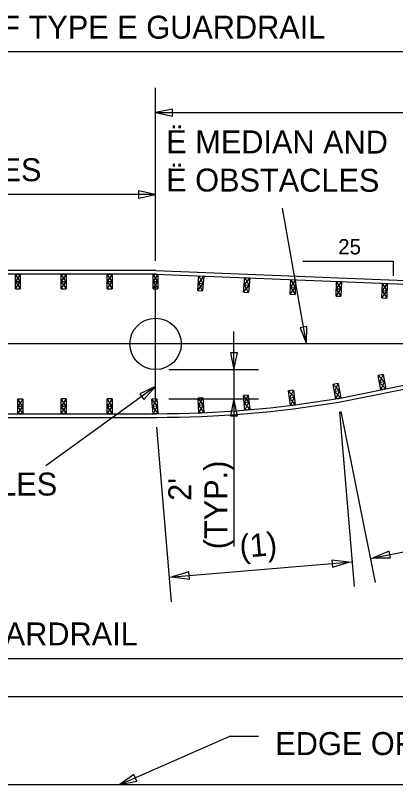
# Model space of a CAD drawing. Extents: x -439.1 to -407.9, y -458.1 to -436.2.
# Drawn here: x -423.51 to -421.03, y -445.9 to -440.88 of the extents above; entities that cross this region are included whole.
import ezdxf

# ---------------------------------------------------------------- set-up
doc = ezdxf.new("R2010")
doc.units = 0
doc.layers.add('Default', color=7, linetype='Continuous')

msp = doc.modelspace()

# ---------------------------------------------------------------- linework, layer by layer
at = {"layer": 'Default'}
for p, q in [((-419.0018, -441.115), (-427.37, -441.115)), ((-422.5989, -442.4799), (-422.5989, -441.3503)), ((-422.5989, -441.5115), (-419.0018, -441.5115)), ((-422.5989, -442.047), (-424.9989, -442.047)), ((-421.6129, -443.0234), (-421.7698, -442.1369)), ((-421.637, -442.4823), (-421.045, -442.4823)), ((-421.045, -442.4823), (-421.045, -442.5783)), ((-422.598, -442.5433), (-425.002, -442.5433)), ((-422.598, -442.5433), (-413.602, -442.9033)), ((-422.599, -442.5673), (-424.999, -442.5673)), ((-423.5148, -442.5674), (-423.4829, -442.5674)), ((-423.4829, -442.6154), (-423.5148, -442.5674)), ((-423.4829, -442.5674), (-423.5148, -442.6154)), ((-423.5148, -442.6634), (-423.5148, -442.5674)), ((-423.4989, -442.5674), (-423.4989, -442.5674)), ((-423.4829, -442.5674), (-423.4829, -442.5674)), ((-423.4829, -442.5674), (-423.4829, -442.6634)), ((-423.2149, -442.5674), (-423.1829, -442.5674)), ((-423.1829, -442.6154), (-423.2149, -442.5674)), ((-423.1829, -442.5674), (-423.2149, -442.6154)), ((-423.2149, -442.6634), (-423.2149, -442.5674)), ((-423.1989, -442.5674), (-423.1989, -442.5674)), ((-423.1829, -442.5674), (-423.1829, -442.5674)), ((-423.1829, -442.5674), (-423.1829, -442.6634)), ((-422.9149, -442.5674), (-422.8829, -442.5674)), ((-422.8829, -442.6154), (-422.9149, -442.5674)), ((-422.8829, -442.5674), (-422.9149, -442.6154)), ((-422.9149, -442.6634), (-422.9149, -442.5674)), ((-422.8989, -442.5674), (-422.8989, -442.5674)), ((-422.8829, -442.5674), (-422.8829, -442.5674)), ((-422.8829, -442.5674), (-422.8829, -442.6634)), ((-422.6149, -442.5674), (-422.5829, -442.5674)), ((-422.5829, -442.6154), (-422.6149, -442.5674)), ((-422.5829, -442.5674), (-422.6149, -442.6154)), ((-422.6149, -442.6634), (-422.6149, -442.5674)), ((-422.599, -442.5673), (-413.603, -442.9273)), ((-422.5989, -442.5674), (-422.5989, -442.5674)), ((-422.5829, -442.5674), (-422.5829, -442.5674)), ((-422.5829, -442.5674), (-422.5829, -442.6634)), ((-422.3234, -442.6736), (-422.3151, -442.578)), ((-422.2832, -442.5807), (-422.3192, -442.6258)), ((-422.3151, -442.578), (-422.2832, -442.5807)), ((-422.2874, -442.6286), (-422.3151, -442.578)), ((-422.2991, -442.5794), (-422.2991, -442.5794)), ((-422.2832, -442.5807), (-422.2915, -442.6764)), ((-422.2832, -442.5807), (-422.2832, -442.5807)), ((-422.0237, -442.6856), (-422.0153, -442.5899)), ((-421.9834, -442.5927), (-422.0195, -442.6378)), ((-422.0153, -442.5899), (-421.9834, -442.5927)), ((-421.9876, -442.6405), (-422.0153, -442.5899)), ((-421.9994, -442.5913), (-421.9994, -442.5913)), ((-421.9834, -442.5927), (-421.9918, -442.6884)), ((-421.9834, -442.5927), (-421.9834, -442.5927)), ((-421.7189, -442.6987), (-421.7156, -442.6028)), ((-421.6836, -442.6039), (-421.7173, -442.6507)), ((-421.7156, -442.6028), (-421.6836, -442.6039)), ((-421.6853, -442.6519), (-421.7156, -442.6028)), ((-421.6996, -442.6033), (-421.6996, -442.6033)), ((-421.6836, -442.6039), (-421.687, -442.6998)), ((-421.6836, -442.6039), (-421.6836, -442.6039)), ((-423.5148, -442.6154), (-423.4829, -442.6154)), ((-423.5148, -442.6634), (-423.4829, -442.6154)), ((-423.5148, -442.6154), (-423.4829, -442.6634)), ((-423.2149, -442.6154), (-423.1829, -442.6154)), ((-423.2149, -442.6634), (-423.1829, -442.6154)), ((-423.2149, -442.6154), (-423.1829, -442.6634)), ((-422.9149, -442.6154), (-422.8829, -442.6154)), ((-422.9149, -442.6634), (-422.8829, -442.6154)), ((-422.9149, -442.6154), (-422.8829, -442.6634)), ((-422.6149, -442.6154), (-422.5829, -442.6154)), ((-422.6149, -442.6634), (-422.5829, -442.6154)), ((-422.6149, -442.6154), (-422.5829, -442.6634)), ((-422.599, -443.3993), (-422.599, -442.6373)), ((-422.3234, -442.6736), (-422.2874, -442.6286)), ((-422.3192, -442.6258), (-422.2874, -442.6286)), ((-422.3192, -442.6258), (-422.2915, -442.6764)), ((-422.0237, -442.6856), (-421.9876, -442.6405)), ((-422.0195, -442.6378), (-421.9876, -442.6405)), ((-422.0195, -442.6378), (-421.9918, -442.6884)), ((-421.7189, -442.6987), (-421.6853, -442.6519)), ((-421.7173, -442.6507), (-421.6853, -442.6519)), ((-421.7173, -442.6507), (-421.687, -442.6998)), ((-421.4192, -442.7107), (-421.4158, -442.6148)), ((-421.3838, -442.6159), (-421.4175, -442.6627)), ((-421.4158, -442.6148), (-421.3838, -442.6159)), ((-421.3855, -442.6639), (-421.4158, -442.6148)), ((-421.3998, -442.6153), (-421.3998, -442.6153)), ((-421.3838, -442.6159), (-421.3872, -442.7118)), ((-421.3838, -442.6159), (-421.3838, -442.6159)), ((-421.1194, -442.7227), (-421.1161, -442.6268)), ((-421.0841, -442.6279), (-421.1177, -442.6747)), ((-421.1161, -442.6268), (-421.0841, -442.6279)), ((-421.0858, -442.6758), (-421.1161, -442.6268)), ((-421.1001, -442.6273), (-421.1001, -442.6273)), ((-421.0841, -442.6279), (-421.0874, -442.7238)), ((-421.0841, -442.6279), (-421.0841, -442.6279)), ((-423.5148, -442.6634), (-423.4829, -442.6634)), ((-423.2149, -442.6634), (-423.2149, -442.6634)), ((-423.2149, -442.6634), (-423.1829, -442.6634)), ((-422.9149, -442.6634), (-422.9149, -442.6634)), ((-422.9149, -442.6634), (-422.8829, -442.6634)), ((-422.6149, -442.6634), (-422.6149, -442.6634)), ((-422.6149, -442.6634), (-422.5829, -442.6634)), ((-422.3234, -442.6736), (-422.3234, -442.6736)), ((-422.3234, -442.6736), (-422.2915, -442.6764)), ((-422.0237, -442.6856), (-422.0237, -442.6856)), ((-422.0237, -442.6856), (-421.9918, -442.6884)), ((-421.7189, -442.6987), (-421.7189, -442.6987)), ((-421.7189, -442.6987), (-421.687, -442.6998)), ((-421.4192, -442.7107), (-421.3855, -442.6639)), ((-421.4175, -442.6627), (-421.3855, -442.6639)), ((-421.4175, -442.6627), (-421.3872, -442.7118)), ((-421.1194, -442.7227), (-421.0858, -442.6758)), ((-421.1177, -442.6747), (-421.0858, -442.6758)), ((-421.1177, -442.6747), (-421.0874, -442.7238)), ((-421.4192, -442.7107), (-421.4192, -442.7107)), ((-421.4192, -442.7107), (-421.3872, -442.7118)), ((-421.1194, -442.7227), (-421.1194, -442.7227)), ((-421.1194, -442.7227), (-421.0874, -442.7238)), ((-422.0869, -443.1914), (-422.0869, -442.9414)), ((-421.404, -443.3793), (-419.1, -442.9183)), ((-421.4, -443.4033), (-419.095, -442.9423)), ((-413.348, -443.0233), (-434.25, -443.0233)), ((-422.5114, -443.1914), (-421.9257, -443.1914)), ((-422.0869, -443.1914), (-422.0869, -443.382)), ((-421.1121, -443.2235), (-421.1436, -443.2293)), ((-421.1033, -443.2706), (-421.1436, -443.2293)), ((-421.126, -443.3237), (-421.1436, -443.2293)), ((-421.1121, -443.2235), (-421.1348, -443.2765)), ((-421.1121, -443.2235), (-421.1121, -443.2235)), ((-421.1121, -443.2235), (-421.0945, -443.3178)), ((-422.5989, -443.3025), (-423.316, -443.8205)), ((-421.4063, -443.2823), (-421.4377, -443.2882)), ((-421.3975, -443.3295), (-421.4377, -443.2882)), ((-421.4201, -443.3825), (-421.4377, -443.2882)), ((-421.4063, -443.2823), (-421.4289, -443.3353)), ((-421.4063, -443.2823), (-421.4063, -443.2823)), ((-421.4063, -443.2823), (-421.3887, -443.3767)), ((-421.1033, -443.2706), (-421.1348, -443.2765)), ((-421.1348, -443.2765), (-421.0945, -443.3178)), ((-421.126, -443.3237), (-421.1033, -443.2706)), ((-421.993, -443.3573), (-422.0248, -443.3604)), ((-421.9883, -443.4051), (-422.0248, -443.3604)), ((-422.0155, -443.4559), (-422.0248, -443.3604)), ((-421.993, -443.3573), (-422.0201, -443.4082)), ((-421.993, -443.3573), (-421.9836, -443.4528)), ((-421.9929, -443.3573), (-421.9929, -443.3573)), ((-421.698, -443.3259), (-421.7297, -443.3301)), ((-421.6917, -443.3735), (-421.7297, -443.3301)), ((-421.7171, -443.4253), (-421.7297, -443.3301)), ((-421.698, -443.3259), (-421.7234, -443.3777)), ((-421.698, -443.3259), (-421.698, -443.3259)), ((-421.698, -443.3259), (-421.6854, -443.4211)), ((-421.3975, -443.3295), (-421.4289, -443.3353)), ((-421.4289, -443.3353), (-421.3887, -443.3767)), ((-421.4201, -443.3825), (-421.3975, -443.3295)), ((-421.0945, -443.3178), (-421.126, -443.3237)), ((-421.126, -443.3237), (-421.126, -443.3237)), ((-421.1102, -443.3208), (-421.1102, -443.3208)), ((-423.4669, -443.3839), (-423.4989, -443.3839)), ((-423.4669, -443.3839), (-423.4989, -443.4319)), ((-423.4669, -443.4319), (-423.4989, -443.3839)), ((-423.4989, -443.4799), (-423.4989, -443.3839)), ((-423.4669, -443.3839), (-423.4669, -443.3839)), ((-423.4669, -443.3839), (-423.4669, -443.4799)), ((-423.1829, -443.3834), (-423.2149, -443.3834)), ((-423.1829, -443.3834), (-423.2149, -443.4314)), ((-423.1829, -443.4314), (-423.2149, -443.3834)), ((-423.2149, -443.4794), (-423.2149, -443.3834)), ((-423.1829, -443.3834), (-423.1829, -443.3834)), ((-423.1829, -443.3834), (-423.1829, -443.4794)), ((-422.8829, -443.3834), (-422.9149, -443.3834)), ((-422.8829, -443.3834), (-422.9149, -443.4314)), ((-422.8829, -443.4314), (-422.9149, -443.3834)), ((-422.9149, -443.4794), (-422.9149, -443.3834)), ((-422.8829, -443.3834), (-422.8829, -443.3834)), ((-422.8829, -443.3834), (-422.8829, -443.4794)), ((-422.5906, -443.3824), (-422.6225, -443.3849)), ((-422.5867, -443.4302), (-422.6225, -443.3849)), ((-422.6148, -443.4806), (-422.6225, -443.3849)), ((-422.5906, -443.3824), (-422.6186, -443.4328)), ((-422.5906, -443.3824), (-422.5906, -443.3824)), ((-422.5906, -443.3824), (-422.5829, -443.4781)), ((-422.5123, -443.382), (-421.9257, -443.382)), ((-422.289, -443.3763), (-422.3209, -443.3783)), ((-422.286, -443.4242), (-422.3209, -443.3783)), ((-422.3149, -443.4741), (-422.3209, -443.3783)), ((-422.289, -443.3763), (-422.3179, -443.4262)), ((-422.289, -443.3763), (-422.289, -443.3763)), ((-422.289, -443.3763), (-422.283, -443.4721)), ((-422.0869, -443.382), (-422.0869, -444.3476)), ((-421.9883, -443.4051), (-422.0201, -443.4082)), ((-422.0201, -443.4082), (-421.9836, -443.4528)), ((-422.0155, -443.4559), (-421.9883, -443.4051)), ((-421.6917, -443.3735), (-421.7234, -443.3777)), ((-421.7234, -443.3777), (-421.6854, -443.4211)), ((-421.7171, -443.4253), (-421.6917, -443.3735)), ((-421.3887, -443.3767), (-421.4201, -443.3825)), ((-421.4201, -443.3825), (-421.4201, -443.3825)), ((-421.4044, -443.3796), (-421.4044, -443.3796)), ((-423.4669, -443.4319), (-423.4989, -443.4319)), ((-423.4989, -443.4319), (-423.4669, -443.4799)), ((-423.4989, -443.4799), (-423.4669, -443.4319)), ((-423.1829, -443.4314), (-423.2149, -443.4314)), ((-423.2149, -443.4314), (-423.1829, -443.4794)), ((-423.2149, -443.4794), (-423.1829, -443.4314)), ((-422.8829, -443.4314), (-422.9149, -443.4314)), ((-422.9149, -443.4314), (-422.8829, -443.4794)), ((-422.9149, -443.4794), (-422.8829, -443.4314)), ((-422.5867, -443.4302), (-422.6186, -443.4328)), ((-422.6186, -443.4328), (-422.5829, -443.4781)), ((-422.6148, -443.4806), (-422.5867, -443.4302)), ((-422.286, -443.4242), (-422.3179, -443.4262)), ((-422.3179, -443.4262), (-422.283, -443.4721)), ((-422.3149, -443.4741), (-422.286, -443.4242)), ((-421.9836, -443.4528), (-422.0155, -443.4559)), ((-422.0155, -443.4559), (-422.0155, -443.4559)), ((-421.9996, -443.4544), (-421.9996, -443.4544)), ((-421.6854, -443.4211), (-421.7171, -443.4253)), ((-421.7171, -443.4253), (-421.7171, -443.4253)), ((-421.7012, -443.4232), (-421.7012, -443.4232)), ((-424.999, -443.4793), (-422.599, -443.4793)), ((-424.999, -443.5033), (-422.589, -443.5033)), ((-423.4989, -443.4799), (-423.4989, -443.4799)), ((-423.4669, -443.4799), (-423.4989, -443.4799)), ((-423.4829, -443.4799), (-423.4829, -443.4799)), ((-423.2149, -443.4794), (-423.2149, -443.4794)), ((-423.1829, -443.4794), (-423.2149, -443.4794)), ((-423.1989, -443.4794), (-423.1989, -443.4794)), ((-422.9149, -443.4794), (-422.9149, -443.4794)), ((-422.8829, -443.4794), (-422.9149, -443.4794)), ((-422.8989, -443.4794), (-422.8989, -443.4794)), ((-422.5829, -443.4781), (-422.6148, -443.4806)), ((-422.6148, -443.4806), (-422.6148, -443.4806)), ((-422.5989, -443.4794), (-422.5989, -443.4794)), ((-422.283, -443.4721), (-422.3149, -443.4741)), ((-422.3149, -443.4741), (-422.3149, -443.4741)), ((-422.2989, -443.4731), (-422.2989, -443.4731)), ((-421.3971, -443.4668), (-421.3018, -444.6086)), ((-421.3873, -443.4654), (-421.1637, -444.5831)), ((-422.5916, -443.5666), (-422.4962, -444.7083)), ((-421.1953, -444.4251), (-420.0186, -444.1897)), ((-422.5096, -444.5477), (-421.3152, -444.4479)), ((-428.596, -445.0799), (-420.2277, -445.0799)), ((-437.226, -445.3273), (-410.372, -445.3273)), ((-422.8326, -445.9034), (-422.1176, -445.5898)), ((-421.926, -445.5893), (-422.118, -445.5893)), ((-437.226, -445.9033), (-410.372, -445.9033))]:
    msp.add_line(p, q, dxfattribs=at)
for points in [[(-422.4882, -441.4885), (-422.5989, -441.5115), (-422.4882, -441.5344)], [(-422.7095, -442.07), (-422.5989, -442.047), (-422.7095, -442.024)], [(-421.6548, -442.9184), (-421.6129, -443.0234), (-421.6096, -442.9104)], [(-422.1099, -443.0807), (-422.0869, -443.1914), (-422.064, -443.0807)], [(-422.6751, -443.3859), (-422.5989, -443.3025), (-422.702, -443.3486)], [(-422.064, -443.4927), (-422.0869, -443.382), (-422.1099, -443.4927)], [(-421.0717, -444.3769), (-421.1757, -444.4211), (-421.0627, -444.422)], [(-421.4434, -444.4817), (-421.3351, -444.4496), (-421.4473, -444.4359)], [(-422.3813, -444.5139), (-422.4897, -444.546), (-422.3775, -444.5597)], [(-422.7405, -445.8379), (-422.8326, -445.9034), (-422.7221, -445.88)]]:
    msp.add_lwpolyline(points, close=True, dxfattribs=at)
msp.add_circle((-422.5989, -443.0234), 0.168, dxfattribs=at)
for radius in [7.2, 7.224]:
    msp.add_arc((-422.5989, -436.2794), radius, 270.00002, 279.54932, dxfattribs=at)

# ---------------------------------------------------------------- texts
for s, height, p in [('LIMITS OF TYPE E GUARDRAIL', 0.15, (-424.4651, -441.0288)), ('25', 0.1, (-421.4051, -442.4384)), ('OBSTACLES', 0.15, (-424.4454, -444.0143)), ('LIMITS OF TYPE E GUARDRAIL', 0.15, (-425.691, -444.9937)), ('EDGE OF TRAVELED WAY', 0.15, (-421.8163, -445.71))]:
    msp.add_text(s, height=height, dxfattribs=at).set_placement(p)
for s, rotation, p in [('Ë MEDIAN AND', 359.9, (-422.5291, -441.7771)), ('VARIES', 0.1, (-424.0802, -441.9613)), ('Ë OBSTACLES', 359.9, (-422.5295, -442.0271)), ('(TYP.)', 90, (-422.1297, -444.3655)), ("2'", 90, (-422.3652, -444.0494)), ('(1)', 4.8, (-422.0441, -444.4224))]:
    msp.add_text(s, height=0.15, rotation=rotation, dxfattribs=at).set_placement(p)

doc.saveas('drawing.dxf')
